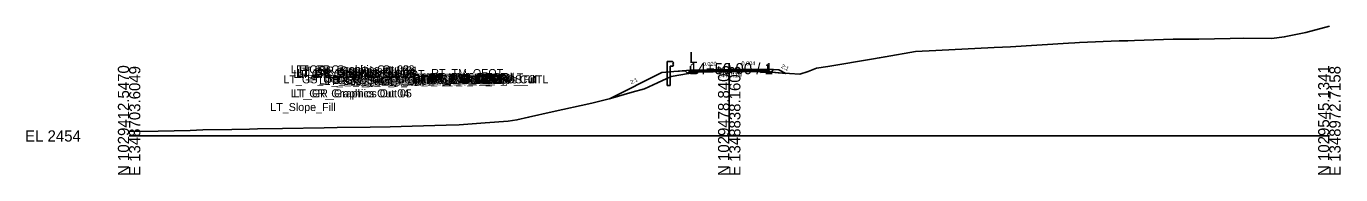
# Model space of a CAD drawing. Extents: x -26 to 1453, y -10 to 4527.
# Drawn here: x -25.7 to 302.8, y 4490.3 to 4527.4 of the extents above; entities that cross this region are included whole.
import ezdxf

# ---------------------------------------------------------------- set-up
doc = ezdxf.new("R2010")
doc.units = 0
for name, color, linetype in [('Default', 7, 'Continuous'), ('Exist CMT Pavement', 7, 'Continuous'), ('Exist Cross Section Cell', 7, 'Continuous'), ('Exist XS Center Line Elevation Label', 7, 'Continuous'), ('Exist XS Ground Line', 7, 'Continuous'), ('Prop CMT Guardrail Graphics', 7, 'Continuous'), ('Prop CMT Pvmt Course 1', 7, 'Continuous'), ('Prop CMT Pvmt Course 1 Wedge', 7, 'Continuous'), ('Prop CMT Pvmt Course 2', 7, 'Continuous'), ('Prop CMT Pvmt Course 2 Wedge', 7, 'Continuous'), ('Prop CMT Pvmt Course 3', 7, 'Continuous'), ('Prop CMT Pvmt Surface', 7, 'Continuous'), ('Prop CMT Pvmt Surface Shoulder', 7, 'Continuous'), ('Prop CMT Pvmt Wedge Surface 1', 7, 'Continuous'), ('Prop CMT Pvmt Wedge Surface 2', 7, 'Continuous'), ('Prop CMT Pvmt Wedge Surface 3', 7, 'Continuous'), ('Prop CMT Shld Paved Course 1', 7, 'Continuous'), ('Prop CMT Shld Paved Course 2', 7, 'Continuous'), ('Prop CMT Shld Paved Course 3', 7, 'Continuous'), ('Prop CMT Slope Grass', 7, 'Continuous'), ('Prop CMT Subgrade Earthwork', 7, 'Continuous'), ('Prop XS Earthwork Shape', 7, 'Continuous'), ('Prop XS EOT Tick Mark', 7, 'Continuous'), ('Prop XS SE Text', 7, 'Continuous'), ('Prop XS Side Slope Text', 7, 'Continuous')]:
    doc.layers.add(name, color=color, linetype=linetype)

msp = doc.modelspace()

# ---------------------------------------------------------------- linework, layer by layer
at = {"layer": 'Exist CMT Pavement'}
for points in [[(150, 4516.19), (149.6, 4516.18), (149.12, 4516.17), (146.03, 4516.11), (142.94, 4516.05), (142.06, 4516.04)], [(150, 4516.19), (150.47, 4516.21), (150.87, 4516.21), (153.9, 4516.21), (156.94, 4516.21), (157.67, 4516.21), (157.81, 4516.21)]]:
    msp.add_lwpolyline(points, dxfattribs=at)
at = {"layer": 'Exist Cross Section Cell'}
for p, q in [((150, 4500), (150, 4518.23)), ((0, 4500), (150, 4500)), ((150, 4500), (300, 4500))]:
    msp.add_line(p, q, dxfattribs=at)
at = {"layer": 'Exist XS Ground Line'}
msp.add_lwpolyline([(0, 4501.08), (7.29, 4501.2), (15.29, 4501.39), (18.42, 4501.49), (25.67, 4501.62), (30.1, 4501.73), (32.1, 4501.79), (38.32, 4501.89), (48.73, 4502.05), (52.01, 4502.11), (60.27, 4502.18), (65.22, 4502.28), (70.76, 4502.47), (79.29, 4502.68), (82.52, 4502.75), (89.04, 4503.24), (94.72, 4503.66), (96.94, 4504), (99.85, 4504.66), (105.77, 4506.07), (115.65, 4508.24), (120.35, 4509.37), (125.72, 4510.93), (128.8, 4511.75), (132.05, 4513.26), (135.49, 4514.9), (139.79, 4515.63), (140.38, 4515.85), (141.55, 4516.03), (149.6, 4516.18), (150, 4516.19), (150.47, 4516.21), (157.67, 4516.21), (158.31, 4516.22), (158.9, 4516.16), (162.22, 4515.77), (162.51, 4515.75), (167.66, 4515.43), (169.71, 4516.15), (171.83, 4516.93), (174.65, 4517.38), (186.1, 4519.29), (187.51, 4519.5), (188.95, 4519.79), (196.56, 4521.09), (201.63, 4521.33), (216.24, 4522.12), (218.34, 4522.21), (220.33, 4522.31), (234.82, 4523.21), (236.42, 4523.32), (237.52, 4523.35), (247.47, 4523.75), (248.97, 4523.81), (249.62, 4523.82), (251.33, 4523.88), (260.95, 4524.18), (267.41, 4524.23), (275.18, 4524.36), (278.66, 4524.43), (285.61, 4524.39), (288.72, 4524.77), (294.11, 4525.87), (300, 4527.42)], dxfattribs=at)
at = {"layer": 'Prop CMT Guardrail Graphics'}
for points in [[(134.53, 4512.58), (134.53, 4518.58)], [(134.53, 4518.58), (135.86, 4518.58), (136.13, 4518.29)], [(136.13, 4517.71), (135.86, 4517.42), (135.2, 4517.42)], [(135.2, 4517.42), (135.2, 4512.58)], [(136.13, 4518.29), (135.86, 4518)], [(135.86, 4518), (136.13, 4517.71)], [(135.2, 4512.58), (134.53, 4512.58)]]:
    msp.add_lwpolyline(points, dxfattribs=at)
at = {"layer": 'Prop CMT Pvmt Course 1'}
for points in [[(150, 4516.61), (140.36, 4516.42)], [(140.36, 4516.42), (140.36, 4516.17)], [(140.36, 4516.17), (142.06, 4516.21)], [(142.06, 4516.33), (150, 4516.49)], [(142.06, 4516.21), (142.06, 4516.33)], [(150, 4516.61), (159.63, 4516.66)], [(150, 4516.49), (150, 4516.61)], [(150, 4516.49), (150, 4516.61)], [(157.81, 4516.52), (150, 4516.49)], [(157.81, 4516.4), (157.81, 4516.52)], [(159.63, 4516.41), (157.81, 4516.4)], [(159.63, 4516.66), (159.63, 4516.41)]]:
    msp.add_lwpolyline(points, dxfattribs=at)
at = {"layer": 'Prop CMT Pvmt Course 1 Wedge'}
for points in [[(142.06, 4516.33), (149.6, 4516.48), (150, 4516.49)], [(150, 4516.36), (149.6, 4516.36), (142.06, 4516.21)], [(142.06, 4516.21), (142.06, 4516.33)], [(150, 4516.49), (150.47, 4516.49), (157.67, 4516.52), (157.81, 4516.52)], [(150, 4516.49), (150, 4516.36)], [(150, 4516.36), (150, 4516.49)], [(157.81, 4516.4), (157.67, 4516.4), (150.47, 4516.37), (150, 4516.36)], [(157.81, 4516.52), (157.81, 4516.4)]]:
    msp.add_lwpolyline(points, dxfattribs=at)
at = {"layer": 'Prop CMT Pvmt Course 2'}
for points in [[(142.06, 4516.21), (140.36, 4516.17)], [(140.36, 4516.17), (140.36, 4515.92)], [(140.36, 4515.92), (142.06, 4515.96)], [(142.06, 4515.96), (142.06, 4516.21)], [(157.81, 4516.4), (159.63, 4516.41)], [(157.81, 4516.15), (157.81, 4516.4)], [(159.63, 4516.16), (157.81, 4516.15)], [(159.63, 4516.41), (159.63, 4516.16)]]:
    msp.add_lwpolyline(points, dxfattribs=at)
at = {"layer": 'Prop CMT Pvmt Course 2 Wedge'}
for points in [[(142.06, 4516.21), (149.6, 4516.36), (150, 4516.36)], [(142.06, 4516.04), (142.06, 4516.21)], [(150, 4516.19), (149.6, 4516.18), (142.06, 4516.04)], [(150, 4516.36), (150.47, 4516.37), (157.67, 4516.4), (157.81, 4516.4)], [(150, 4516.36), (150, 4516.19)], [(150, 4516.19), (150, 4516.36)], [(157.81, 4516.21), (157.67, 4516.21), (150.47, 4516.21), (150, 4516.19)], [(157.81, 4516.4), (157.81, 4516.21)]]:
    msp.add_lwpolyline(points, dxfattribs=at)
at = {"layer": 'Prop CMT Pvmt Course 3'}
for points in [[(142.06, 4515.96), (140.36, 4515.92)], [(140.36, 4515.92), (140.36, 4515.67)], [(140.36, 4515.67), (142.06, 4515.71)], [(142.06, 4515.71), (142.06, 4515.96)], [(157.81, 4516.15), (159.63, 4516.16)], [(157.81, 4515.9), (157.81, 4516.15)], [(159.63, 4515.91), (157.81, 4515.9)], [(159.63, 4516.16), (159.63, 4515.91)]]:
    msp.add_lwpolyline(points, dxfattribs=at)
at = {"layer": 'Prop CMT Pvmt Surface'}
for points in [[(150, 4516.61), (140.36, 4516.42)], [(150, 4516.61), (159.63, 4516.66)]]:
    msp.add_lwpolyline(points, dxfattribs=at)
at = {"layer": 'Prop CMT Pvmt Surface Shoulder'}
for points in [[(140.36, 4516.42), (140.36, 4516.42)], [(159.63, 4516.66), (159.63, 4516.66)]]:
    msp.add_lwpolyline(points, dxfattribs=at)
at = {"layer": 'Prop CMT Pvmt Wedge Surface 1'}
for points in [[(142.06, 4516.46), (140.36, 4516.42)], [(150, 4516.49), (142.06, 4516.33)], [(142.06, 4516.33), (142.06, 4516.46)], [(150, 4516.49), (157.81, 4516.52)], [(157.81, 4516.65), (159.63, 4516.66)], [(157.81, 4516.52), (157.81, 4516.65)]]:
    msp.add_lwpolyline(points, dxfattribs=at)
at = {"layer": 'Prop CMT Pvmt Wedge Surface 2'}
for points in [[(140.36, 4516.17), (140.36, 4516.42)], [(150, 4516.36), (142.06, 4516.21), (140.36, 4516.17)], [(150, 4516.36), (157.81, 4516.4), (159.63, 4516.41)], [(159.63, 4516.41), (159.63, 4516.66)]]:
    msp.add_lwpolyline(points, dxfattribs=at)
at = {"layer": 'Prop CMT Pvmt Wedge Surface 3'}
for points in [[(140.36, 4515.92), (140.36, 4516.42)], [(150, 4516.11), (142.06, 4515.96), (140.36, 4515.92)], [(150, 4516.11), (157.81, 4516.15), (159.63, 4516.16)], [(159.63, 4516.16), (159.63, 4516.66)]]:
    msp.add_lwpolyline(points, dxfattribs=at)
at = {"layer": 'Prop CMT Shld Paved Course 1'}
for points in [[(140.36, 4516.42), (140.36, 4516.42), (140.11, 4516.17)], [(140.11, 4516.17), (140.36, 4516.17)], [(140.36, 4516.17), (140.36, 4516.42)], [(159.63, 4516.66), (159.63, 4516.66), (159.88, 4516.41)], [(159.63, 4516.41), (159.63, 4516.66)], [(159.88, 4516.41), (159.63, 4516.41)]]:
    msp.add_lwpolyline(points, dxfattribs=at)
at = {"layer": 'Prop CMT Shld Paved Course 2'}
for points in [[(140.36, 4516.17), (140.11, 4516.17), (139.85, 4515.91)], [(139.85, 4515.91), (140.36, 4515.92)], [(140.36, 4515.92), (140.36, 4516.17)], [(159.63, 4516.41), (159.88, 4516.41), (160.13, 4516.16)], [(159.63, 4516.16), (159.63, 4516.41)], [(160.13, 4516.16), (159.63, 4516.16)]]:
    msp.add_lwpolyline(points, dxfattribs=at)
at = {"layer": 'Prop CMT Shld Paved Course 3'}
for points in [[(139.85, 4515.91), (139.6, 4515.66)], [(139.6, 4515.66), (140.36, 4515.67)], [(140.36, 4515.92), (139.85, 4515.91)], [(139.85, 4515.91), (139.85, 4515.91)], [(140.36, 4515.67), (140.36, 4515.92)], [(159.63, 4516.16), (160.13, 4516.16)], [(159.63, 4515.91), (159.63, 4516.16)], [(160.38, 4515.91), (159.63, 4515.91)], [(160.13, 4516.16), (160.13, 4516.16)], [(160.13, 4516.16), (160.38, 4515.91)]]:
    msp.add_lwpolyline(points, dxfattribs=at)
at = {"layer": 'Prop CMT Slope Grass'}
for points in [[(133.13, 4515.84), (120.04, 4509.3)], [(136.13, 4516.08), (133.13, 4515.84)], [(140.36, 4516.42), (136.13, 4516.08)], [(159.63, 4516.66), (162.41, 4516.5)], [(162.41, 4516.5), (164.11, 4515.65)]]:
    msp.add_lwpolyline(points, dxfattribs=at)
at = {"layer": 'Prop CMT Subgrade Earthwork'}
for points in [[(139.6, 4515.66), (138.95, 4516.31)], [(140.36, 4515.67), (139.6, 4515.66)], [(142.06, 4515.71), (140.36, 4515.67)], [(142.06, 4515.71), (142.06, 4516.04)], [(157.81, 4515.9), (157.81, 4516.21)], [(157.81, 4515.9), (159.63, 4515.91)], [(159.63, 4515.91), (160.38, 4515.91)], [(160.38, 4515.91), (161.05, 4516.58)]]:
    msp.add_lwpolyline(points, dxfattribs=at)
at = {"layer": 'Prop XS Earthwork Shape'}
for points in [[(139.89, 4515.66), (139.6, 4515.66), (138.95, 4516.31), (136.13, 4516.08), (133.13, 4515.84), (120.04, 4509.3), (120.35, 4509.37), (125.72, 4510.93), (128.8, 4511.75), (132.05, 4513.26), (135.49, 4514.9), (139.79, 4515.63)], [(139.89, 4515.66), (139.6, 4515.66), (138.95, 4516.31), (136.13, 4516.08), (133.13, 4515.84), (120.04, 4509.3), (120.35, 4509.37), (125.72, 4510.93), (128.8, 4511.75), (132.05, 4513.26), (135.49, 4514.9), (139.79, 4515.63)], [(142.06, 4515.71), (142.06, 4516.04), (141.55, 4516.03), (140.38, 4515.85), (139.89, 4515.66), (140.36, 4515.67)], [(142.06, 4515.71), (142.06, 4516.04), (141.55, 4516.03), (140.38, 4515.85), (139.89, 4515.66), (140.36, 4515.67)], [(157.81, 4515.9), (159.63, 4515.91), (160.38, 4515.91), (160.45, 4515.98), (158.9, 4516.16), (158.31, 4516.22), (157.81, 4516.21)], [(157.81, 4515.9), (159.63, 4515.91), (160.38, 4515.91), (160.45, 4515.98), (158.9, 4516.16), (158.31, 4516.22), (157.81, 4516.21)], [(160.45, 4515.98), (162.22, 4515.77), (162.51, 4515.75), (164.11, 4515.65), (162.41, 4516.5), (161.05, 4516.58)], [(160.45, 4515.98), (162.22, 4515.77), (162.51, 4515.75), (164.11, 4515.65), (162.41, 4516.5), (161.05, 4516.58)]]:
    msp.add_lwpolyline(points, close=True, dxfattribs=at)
at = {"layer": 'Prop XS EOT Tick Mark'}
for points in [[(140.36, 4516.42), (140.36, 4517.42)], [(159.63, 4516.66), (159.63, 4517.66)]]:
    msp.add_lwpolyline(points, dxfattribs=at)

# ---------------------------------------------------------------- texts
at = {"layer": 'Default'}
for s, height, p in [('LT_GR_Graphics Out 03', 2, (40.43, 4515.65)), ('LT_GR_Graphics Out 02', 2, (41.76, 4515.65)), ('LT_GR_Graphics Out 01', 2, (42.6, 4515.36)), ('LT_GS_OS_GR_Face_Graphics', 2, (38.59, 4513.15)), ('LT_GR_Graphics Out 06', 2, (41.05, 4514.49)), ('LT_GR_Graphics Out 09', 2, (41.76, 4515.07)), ('LT_GR_Graphics Out 07', 2, (41.76, 4514.49)), ('LT_GR_Graphics Out 08', 2, (42.03, 4514.78)), ('LT_Sub_Trench_Out_DLT', 2, (44.51, 4513.38)), ('LT_GS_OS_CTL', 2, (47.5, 4512.91)), ('LT_Sub_Trench_Out', 2, (48.8, 4512.73)), ('LT_PS3_Shelf_Out', 2, (50.84, 4512.98)), ('LT_PV_Sub_Tie_Out', 2, (52, 4513.04)), ('LT_PV_EG_TestPt3', 2, (53.45, 4513.05)), ('LT_PV1_OEEOP_Null', 2, (53.52, 4513.53)), ('LT_PV_OEEOP_EG', 2, (54.6, 4513.04)), ('LT_PV1_OEEOP_W', 2, (55.04, 4513.4)), ('LT_PS3_OEOP', 2, (55.09, 4512.98)), ('LT_PS2_OEOP', 2, (55.34, 4513.24)), ('LT_Sub_OEOT', 2, (55.44, 4512.74)), ('LT_PV2_OEOT', 2, (55.54, 4513.24)), ('LT_PV3_OEOT', 2, (55.54, 4512.99)), ('LT_PV1_OEOT', 2, (56.1, 4513.49)), ('LT_PS1_OEOP', 2, (56.17, 4513.49)), ('LT_Sub_OEEOP', 2, (56.27, 4512.78)), ('LT_TM_OEOT', 2, (56.31, 4514.49)), ('LT_PV2_OEEOP', 2, (56.37, 4513.28)), ('LT_PV3_OEEOP', 2, (56.37, 4513.03)), ('LT_PV_EG_TestPt2', 2, (56.54, 4513.11)), ('LT_PV_EG_TestPt1', 2, (60.2, 4513.17)), ('RT_PV_EG_TestPt1', 2, (61.9, 4513.21)), ('RT_PV_EG_TestPt2', 2, (64.37, 4513.21)), ('PV_EPGL_EG', 2, (66.24, 4513.19)), ('RT_Sub_Trench_Out_DLT', 2, (66.57, 4513.65)), ('PV2_PGL_W', 2, (67.02, 4513.43)), ('PV3_PGL_W', 2, (67.02, 4513.18)), ('RT_PV_EG_TestPt3', 2, (67.41, 4513.21)), ('PV1_PGL_W', 2, (67.58, 4513.56)), ('RT_PV_Sub_Tie_Out', 2, (67.71, 4513.21)), ('RT_PV1_OEEOP_Null', 2, (69.22, 4513.72)), ('PV1_PGL', 2, (69.47, 4513.68)), ('RT_Sub_Trench_Out', 2, (69.54, 4512.98)), ('RT_PV_OEEOP_EG', 2, (70.3, 4513.21)), ('RT_PV1_OEEOP_W', 2, (70.75, 4513.59)), ('RT_PS3_Shelf_Out', 2, (71.07, 4513.23)), ('RT_Sub_OEEOP', 2, (71.97, 4512.97)), ('RT_PV2_OEEOP', 2, (72.07, 4513.47)), ('RT_PV3_OEEOP', 2, (72.07, 4513.22)), ('RT_Sub_OEOT', 2, (74.67, 4512.98)), ('RT_PV2_OEOT', 2, (74.76, 4513.48)), ('RT_PV3_OEOT', 2, (74.76, 4513.23)), ('RT_PS2_OEOP', 2, (75.07, 4513.48)), ('RT_PS3_OEOP', 2, (75.32, 4513.23)), ('RT_PV1_OEOT', 2, (75.33, 4513.73)), ('RT_PS1_OEOP', 2, (75.39, 4513.73)), ('RT_TM_OEOT', 2, (75.53, 4514.73)), ('RT_GS_OS_CTL', 2, (83.96, 4513.17)), ('RT_Slope_Cut', 2, (84.28, 4513.14)), ('RT_Slope_Fill', 2, (85.16, 4513.14)), ('LT_GR_Graphics Out 04', 2, (40.43, 4509.65)), ('LT_GR_Graphics Out 05', 2, (41.09, 4509.65)), ('LT_Slope_Fill', 2, (35.29, 4506.23)), ('-', 0.0001, (0, 4500)), ('-', 0.0001, (0, 4500)), ('-', 0.0001, (0, 4500)), ('-', 0.0001, (0, 4500))]:
    msp.add_text(s, height=height, dxfattribs=at).set_placement(p)
at = {"layer": 'Exist Cross Section Cell'}
for s, p in [('L', (140, 4518.23)), ('14+50.00 / 1', (140, 4515.43)), ('EL 2454', (-26, 4498.6))]:
    msp.add_text(s, height=2.8, dxfattribs=at).set_placement(p)
for s, p in [('N 1029412.5470', (0, 4490)), ('N 1029478.8405', (150, 4490)), ('N 1029545.1341', (300, 4490)), ('E 1348703.6049', (2.8, 4490)), ('E 1348838.1603', (152.8, 4490)), ('E 1348972.7158', (302.8, 4490))]:
    msp.add_text(s, height=2.8, rotation=90, dxfattribs=at).set_placement(p)
at = {"layer": 'Exist XS Center Line Elevation Label'}
msp.add_text('2470.19', height=1.23, dxfattribs=at).set_placement((147.02, 4514.63))
at = {"layer": 'Prop XS SE Text'}
for s, rotation, p in [('0.020', 1.1458, (143.41, 4517.48)), ('0.004', 0.2464, (153.07, 4517.63))]:
    msp.add_text(s, height=1, rotation=rotation, dxfattribs=at).set_placement(p)
at = {"layer": 'Prop XS Side Slope Text'}
for rotation, p in [(333.4349, (162.89, 4517.1)), (26.5651, (125.54, 4512.89))]:
    msp.add_text('2:1', height=1, rotation=rotation, dxfattribs=at).set_placement(p)

doc.saveas('drawing.dxf')
